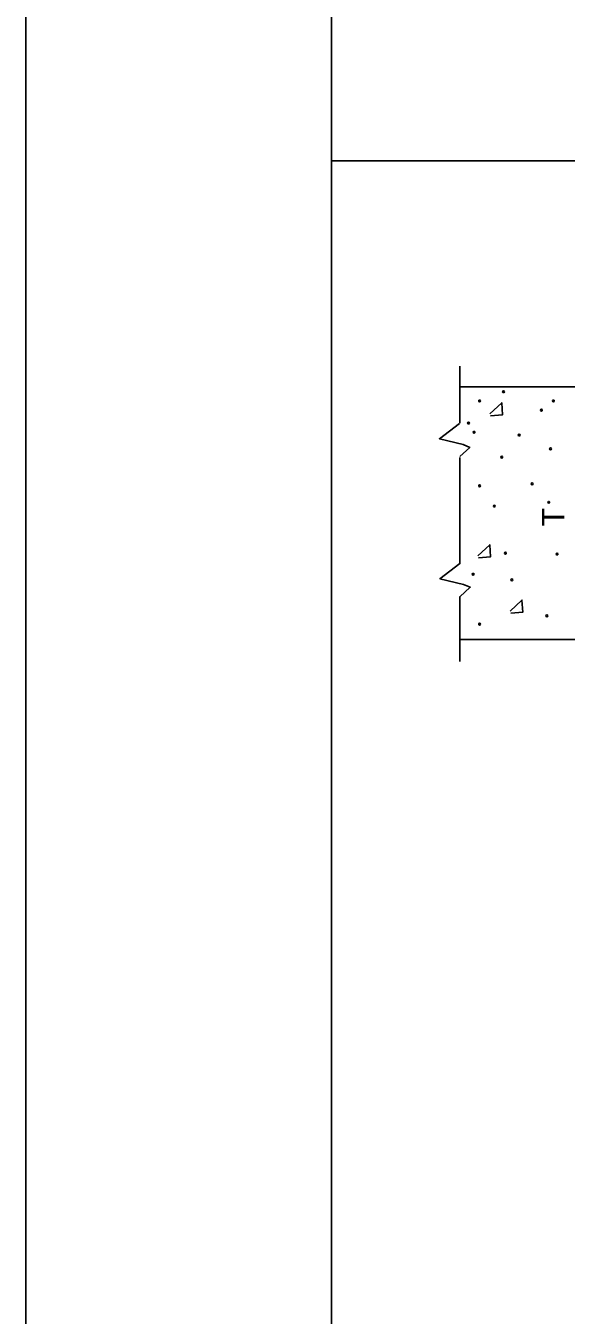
# Model space of a CAD drawing. Extents: x 1375738 to 1375905, y 380661 to 380875.
# Drawn here: x 1375738.22 to 1375749.18, y 380791.35 to 380817.52 of the extents above; entities that cross this region are included whole.
import ezdxf

# ---------------------------------------------------------------- set-up
doc = ezdxf.new("R2010")
doc.units = 0
for name, color, linetype in [('R_Border', 7, 'Continuous'), ('R_Draft', 7, 'Continuous'), ('R_No Plot', 7, 'Continuous')]:
    doc.layers.add(name, color=color, linetype=linetype)

msp = doc.modelspace()

# ---------------------------------------------------------------- linework, layer by layer
at = {"layer": 'R_Border'}
for p, q in [((1375744.419, 380770.053), (1375744.419, 380872.783)), ((1375744.419, 380814.777), (1375786.095, 380814.777))]:
    msp.add_line(p, q, dxfattribs=at)
at = {"layer": 'R_Draft'}
for p, q in [((1375747.021, 380809.452), (1375747.021, 380810.607)), ((1375747.021, 380810.189), (1375759.3, 380810.189)), ((1375747.021, 380806.6), (1375747.021, 380808.759)), ((1375747.021, 380804.614), (1375747.021, 380805.934)), ((1375747.021, 380805.063), (1375771.466, 380805.063))]:
    msp.add_line(p, q, dxfattribs=at)
for points in [[(1375747.63, 380809.642), (1375747.873, 380809.867), (1375747.892, 380809.623), (1375747.649, 380809.605)], [(1375747.014, 380809.443), (1375746.61, 380809.135), (1375747.091, 380809.019), (1375747.226, 380808.961), (1375747.021, 380808.776)], [(1375747.387, 380806.76), (1375747.63, 380806.985), (1375747.649, 380806.741), (1375747.406, 380806.723)], [(1375747.024, 380806.602), (1375746.62, 380806.294), (1375747.101, 380806.179), (1375747.236, 380806.121), (1375747.021, 380805.927)], [(1375748.042, 380805.637), (1375748.285, 380805.862), (1375748.304, 380805.618), (1375748.06, 380805.6)]]:
    msp.add_lwpolyline(points, dxfattribs=at)
for centre in [(1375747.425, 380809.904), (1375747.911, 380810.091), (1375748.922, 380809.904), (1375748.678, 380809.717), (1375747.2, 380809.455), (1375747.312, 380809.268), (1375748.229, 380809.212), (1375748.865, 380808.931), (1375747.874, 380808.762), (1375747.425, 380808.182), (1375748.491, 380808.22), (1375748.828, 380807.846), (1375747.724, 380807.771), (1375747.948, 380806.816), (1375748.997, 380806.797), (1375747.294, 380806.386), (1375748.079, 380806.273), (1375748.791, 380805.544), (1375747.425, 380805.375)]:
    msp.add_circle(centre, 0.0188, dxfattribs=at)
at = {"layer": 'R_No Plot'}
for points in [[(1375738.215, 380874.73), (1375904.885, 380874.73), (1375904.885, 380768.061), (1375738.215, 380768.061)], [(1375861.379, 380872.783), (1375871.189, 380872.783), (1375871.189, 380867.843), (1375879.245, 380867.843), (1375890.845, 380867.843), (1375890.845, 380851.508), (1375902.449, 380851.508), (1375902.509, 380770.053), (1375744.419, 380770.053), (1375744.419, 380872.783)]]:
    msp.add_lwpolyline(points, close=True, dxfattribs=at)

# ---------------------------------------------------------------- texts
at = {"layer": 'R_Draft'}
msp.add_text('T', height=0.452, rotation=90, dxfattribs=at).set_placement((1375749.142, 380807.36))

doc.saveas('drawing.dxf')
